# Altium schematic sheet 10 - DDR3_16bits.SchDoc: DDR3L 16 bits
size A3; Date: 1-DEC-2018; Author: CR; CompanyName: Octavo Systems LLC; Address2: Austin, TX; DocumentNumber: DK2 RefDes; Revision: C-01; SheetNumber: 10; SheetTotal: 14; PageSetup: Record=PageOptions¦CenterHorizontal=True¦CenterVertical=True¦PrintScale=1.39¦XCorrection=1.00¦YCorrection=1.00¦PrintKind=1¦BorderSize=5000000¦LeftOffset=0¦BottomOffset=0¦Orientation=2¦PaperLength=1000¦PaperWidth=1000¦Scale=100¦PaperSource=15¦PrintQuality=600¦MediaType=1¦DitherType=10¦PrintScaleMode=1¦PaperKind=A3¦PaperIndex=8
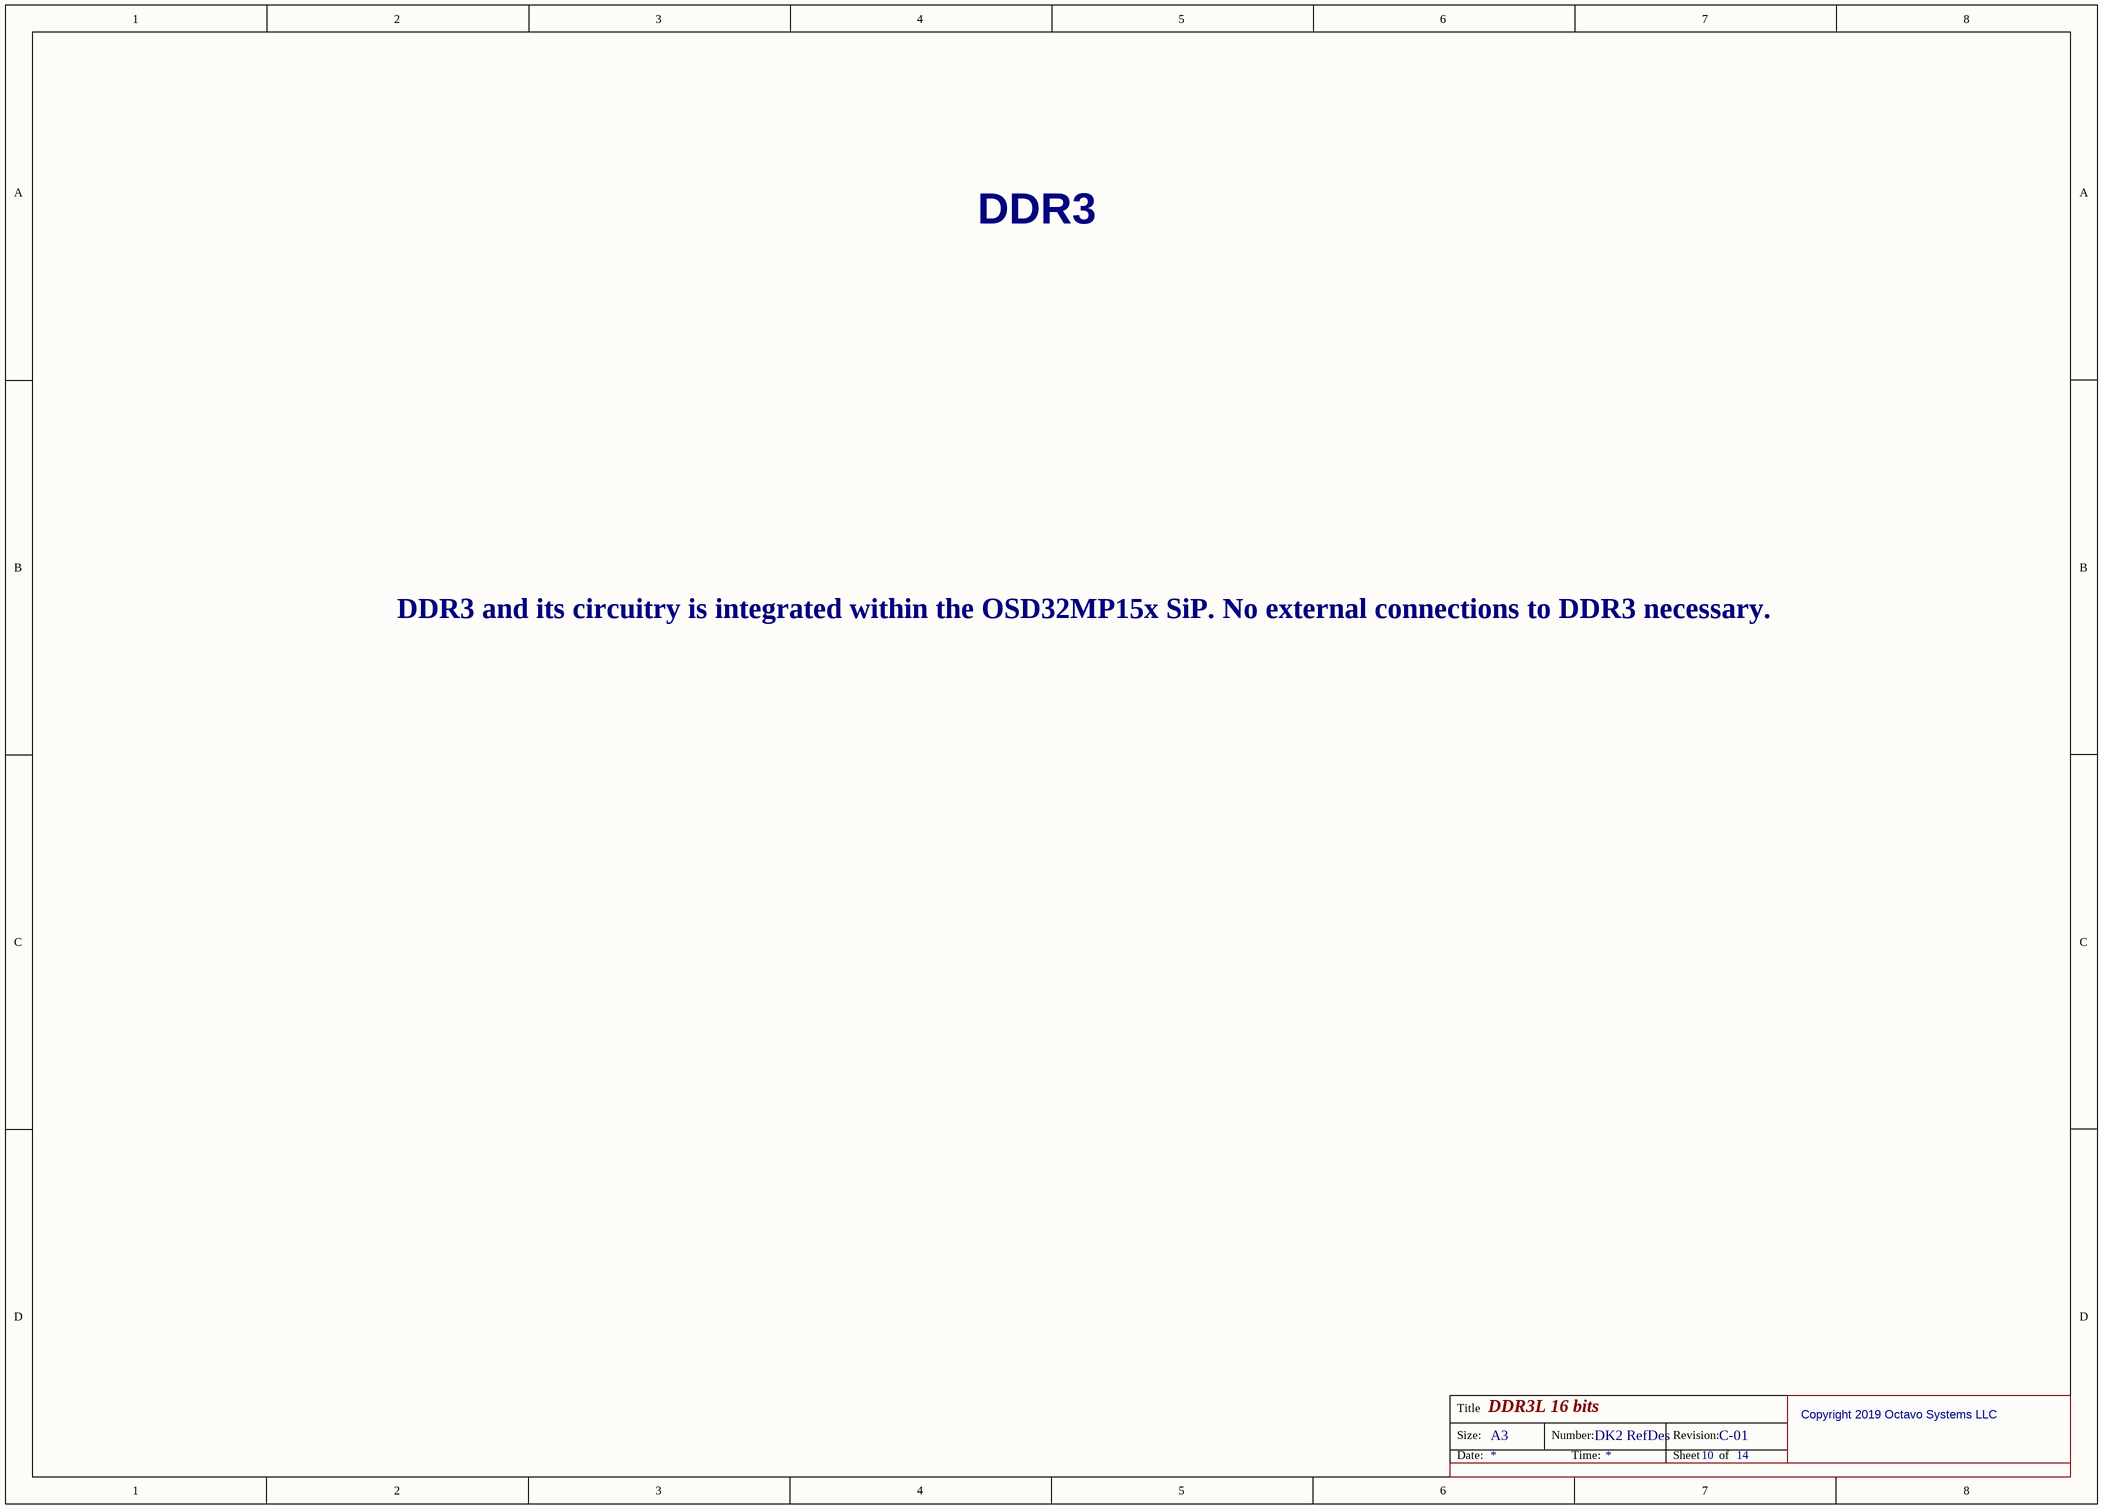
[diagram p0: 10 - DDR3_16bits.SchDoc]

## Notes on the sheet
- DDR3
- DDR3 and its circuitry is integrated within the OSD32MP15x SiP. No external connections to DDR3 necessary.
- Copyright 2019 Octavo Systems LLC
